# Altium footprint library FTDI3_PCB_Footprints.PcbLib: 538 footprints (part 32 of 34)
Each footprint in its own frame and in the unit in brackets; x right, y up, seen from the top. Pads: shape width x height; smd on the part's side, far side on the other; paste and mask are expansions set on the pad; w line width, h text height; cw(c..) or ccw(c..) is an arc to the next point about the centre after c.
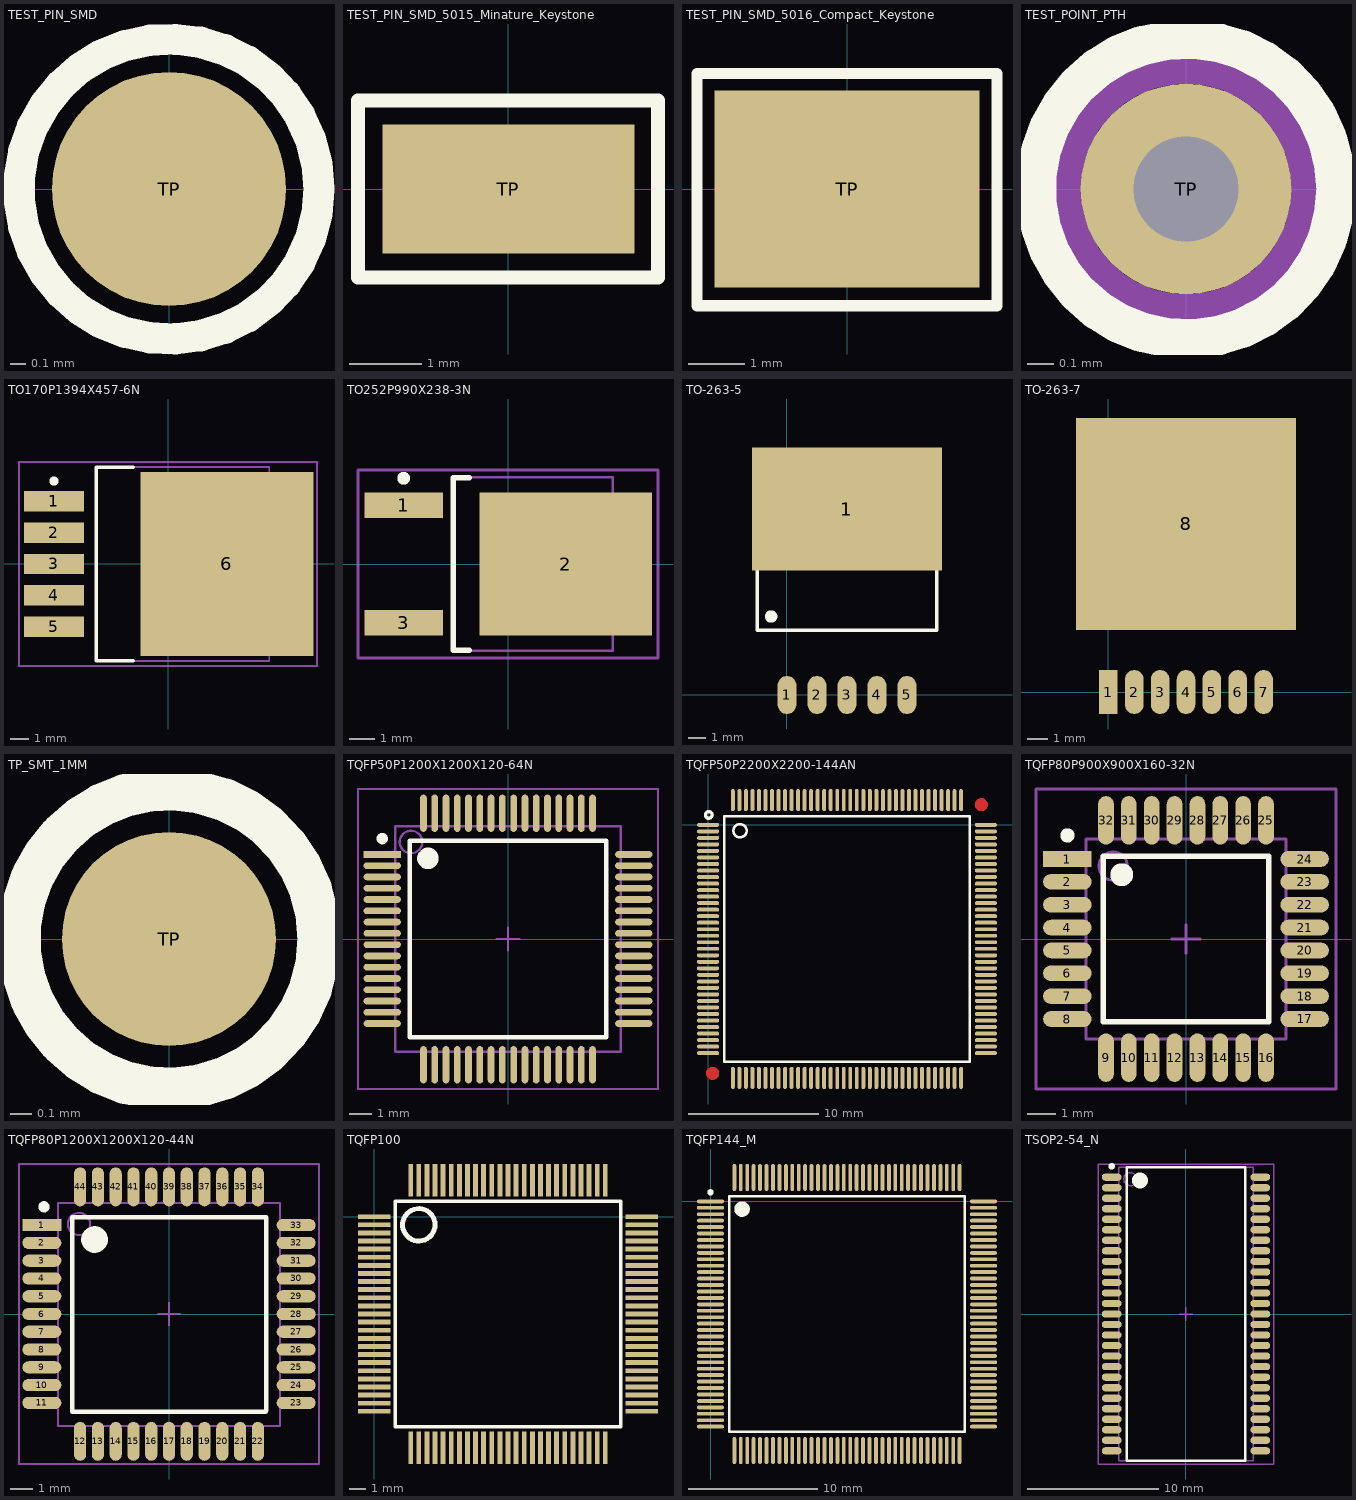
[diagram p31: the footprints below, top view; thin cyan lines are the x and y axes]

## TEST_PIN_SMD [mm] "Test pin; SMD"
pads (1):
  round 1.5 smd: TP(0,0)
Top Overlay:
  circle w0.2: c0,0 r0.96
M13_Assembly_Info keep-out:
  circle w0.1: c0,0 r0.96
3D body: height 0, standoff 0, extent -0.96,-0.97 0.96,0.95

## TEST_PIN_SMD_5015_Minature_Keystone [mm] "Test pin; SMD; 5015; Keystone"
height 1.52
pads (1):
  rect 3.5x1.8 smd: TP(0,0)
Top Overlay:
  lines w0.2: -2.09,-1.23 2.08,-1.23 2.08,1.23 -2.09,1.23 -2.09,-1.23

## TEST_PIN_SMD_5016_Compact_Keystone [mm] "Test pin; SMD; 5016; Keystone"
pads (1):
  rect 4.7x3.5 smd: TP(0,0)
Top Overlay:
  lines w0.2: -2.66,-2.07 -2.66,2.05 2.66,2.05 2.66,-2.07 -2.66,-2.07

## TEST_POINT_PTH [mm] "Test point for scope probe"
height 4.6
pads (1):
  round 0.8 hole 0.4: TP(0,0)
Top Overlay:
  circle w0.15: c0,0 r0.57
M13_Assembly_Info:
  circle w0.1: c0,0 r0.45

## TO170P1394X457-6N [mm] "D2-PAK, 6-Pads, Body 9.4x10.5mm (max), IPC Medium Density"
height 4.572
pads (6):
  rect 3.25x1.1 smd: 1(-6.2,3.404) 2(-6.2,1.702) 3(-6.2,0) 4(-6.2,-1.702) 5(-6.2,-3.404)
  rect 9.4x10 smd: 6(3.2,0)
Top Overlay:
  circle w0.25: c-6.2,4.504 r0.125
  lines w0.2: -1.9,-5.25 -3.9,-5.25 -3.9,5.25 -1.9,5.25
M13_Assembly_Info:
  lines w0.1: -3.9,-5.275 5.5,-5.275 5.5,5.275 -3.9,5.275 -3.9,-5.275
M15_Country_Yard:
  lines w0.1: -0.5,0 0.5,0 ; 0,-0.5 0,0.5 ; -8.1,-5.55 8.1,-5.55 8.1,5.55 -8.1,5.55 -8.1,-5.55
3D body: height 4.57, standoff 0.31, extent -3.9,-5.275 5.5,5.275

## TO252P990X238-3N [mm] "D-PAK, 3-Pads, Body 6.2x6.7mm (max), IPC Medium Density"
height 2.38
pads (3):
  rect 3.05x1 smd: 1(-4.05,2.28) 3(-4.05,-2.28)
  rect 6.7x5.55 smd: 2(2.25,0)
Top Overlay:
  circle w0.25: c-4.05,3.33 r0.125
  lines w0.2: -1.5,-3.35 -2.125,-3.35 -2.125,3.35 -1.5,3.35
M13_Assembly_Info:
  lines w0.1: -2.15,-3.375 4.07,-3.375 4.07,3.375 -2.15,3.375 -2.15,-3.375
M15_Country_Yard:
  lines w0.1: -0.5,0 0.5,0 ; 0,-0.5 0,0.5 ; -5.825,-3.65 5.825,-3.65 5.825,3.65 -5.825,3.65 -5.825,-3.65
3D body: height 2.38, standoff 0.13, extent -2.15,-3.375 4.07,3.375

## TO-263-5 [mil]
pads (6):
  oval 42x85 smd: 1(0,0) 2(67,0) 3(134,0) 4(201,0) 5(268,0)
  rect 425x275 smd: 1(134.02,415)
Top Overlay:
  circle w19.68: c-35.43,175.2 r3.94
  lines w7.87: -66,460 334,460 ; -66,145 334,145 334,485 -66,485 -66,145

## TO-263-7 [mil] "TO-263-7pin SMT package"
pads (8):
  rect 35.98x85 smd: 1(0,0)
  oval 36x85 smd: 2(50,0) 3(100,0) 4(150,0) 5(200,0) 6(250,0) 7(300,0)
  rect 425x410 smd: 8(150,325)
Top Overlay:
  circle w10: c-20,160 r10
  lines w7.87: -50,440 350,440 ; -50,130 -50,470 350,470 350,130 -50,130

## TP_SMT_1MM [mm]
pads (1):
  round 1 smd paste-1: TP(0,0)
Top Overlay:
  circle w0.2: c0,0 r0.7

## TQFP50P1200X1200X120-64N [mm] "TQFP, 64-Leads, Body 12.0x12.0mm (max), Pitch 0.50mm, IPC Medium Density"
height 1.2
pads (64):
  rect 1.65x0.3 smd: 1(-5.575,3.75)
  oval 1.65x0.3 smd: 2(-5.575,3.25) 3(-5.575,2.75) 4(-5.575,2.25) 5(-5.575,1.75) 6(-5.575,1.25) 7(-5.575,0.75) 8(-5.575,0.25) 9(-5.575,-0.25) 10(-5.575,-0.75) 11(-5.575,-1.25) 12(-5.575,-1.75) 13(-5.575,-2.25) 14(-5.575,-2.75) 15(-5.575,-3.25) 16(-5.575,-3.75) 33(5.575,-3.75) 34(5.575,-3.25) 35(5.575,-2.75) 36(5.575,-2.25) 37(5.575,-1.75) 38(5.575,-1.25) 39(5.575,-0.75) 40(5.575,-0.25) 41(5.575,0.25) 42(5.575,0.75) 43(5.575,1.25) 44(5.575,1.75) 45(5.575,2.25) 46(5.575,2.75) 47(5.575,3.25) 48(5.575,3.75)
  oval 0.3x1.65 smd: 17(-3.75,-5.575) 18(-3.25,-5.575) 19(-2.75,-5.575) 20(-2.25,-5.575) 21(-1.75,-5.575) 22(-1.25,-5.575) 23(-0.75,-5.575) 24(-0.25,-5.575) 25(0.25,-5.575) 26(0.75,-5.575) 27(1.25,-5.575) 28(1.75,-5.575) 29(2.25,-5.575) 30(2.75,-5.575) 31(3.25,-5.575) 32(3.75,-5.575) 49(3.75,5.575) 50(3.25,5.575) 51(2.75,5.575) 52(2.25,5.575) 53(1.75,5.575) 54(1.25,5.575) 55(0.75,5.575) 56(0.25,5.575) 57(-0.25,5.575) 58(-0.75,5.575) 59(-1.25,5.575) 60(-1.75,5.575) 61(-2.25,5.575) 62(-2.75,5.575) 63(-3.25,5.575) 64(-3.75,5.575)
Top Overlay:
  circle w0.25: c-5.575,4.45 r0.125
  circle w0.6: c-3.55,3.575 r0.175
  lines w0.2: -4.35,-4.35 -4.35,4.35 4.35,4.35 4.35,-4.35 -4.35,-4.35
M13_Assembly_Info:
  circle w0.1: c-4.3,4.3 r0.5
  lines w0.1: -5,-5 -5,5 5,5 5,-5 -5,-5
M15_Country_Yard:
  lines w0.1: -0.5,0 0.5,0 ; 0,-0.5 0,0.5 ; -6.65,-6.65 -6.65,6.65 6.65,6.65 6.65,-6.65 -6.65,-6.65
3D body: height 1.2, standoff 0.15, extent -5,-5 5,5

## TQFP50P2200X2200-144AN [mm] "Thin QFP, 144-Leads, Body 20x20mm, Pitch 0.5mm"
pads (144):
  oval 1.7x0.3 smd: 1(0,0) 2(0,-0.5) 3(0,-1) 4(0,-1.5) 5(0,-2) 6(0,-2.5) 7(0,-3) 8(0,-3.5) 9(0,-4) 10(0,-4.5) 11(0,-5) 12(0,-5.5) 13(0,-6) 14(0,-6.5) 15(0,-7) 16(0,-7.5) 17(0,-8) 18(0,-8.5) 19(0,-9) 20(0,-9.5) 21(0,-10) 22(0,-10.5) 23(0,-11) 24(0,-11.5) 25(0,-12) 26(0,-12.5) 27(0,-13) 28(0,-13.5) 29(0,-14) 30(0,-14.5) 31(0,-15) 32(0,-15.5) 33(0,-16) 34(0,-16.5) 35(0,-17) 36(0,-17.5) 73(21.3,-17.5) 74(21.3,-17) 75(21.3,-16.5) 76(21.3,-16) 77(21.3,-15.5) 78(21.3,-15) 79(21.3,-14.5) 80(21.3,-14) 81(21.3,-13.5) 82(21.3,-13) 83(21.3,-12.5) 84(21.3,-12) 85(21.3,-11.5) 86(21.3,-11) 87(21.3,-10.5) 88(21.3,-10) 89(21.3,-9.5) 90(21.3,-9) 91(21.3,-8.5) 92(21.3,-8) 93(21.3,-7.5) 94(21.3,-7) 95(21.3,-6.5) 96(21.3,-6) 97(21.3,-5.5) 98(21.3,-5) 99(21.3,-4.5) 100(21.3,-4) 101(21.3,-3.5) 102(21.3,-3) 103(21.3,-2.5) 104(21.3,-2) 105(21.3,-1.5) 106(21.3,-1) 107(21.3,-0.5) 108(21.3,0)
  oval 0.3x1.7 smd: 37(1.9,-19.4) 38(2.4,-19.4) 39(2.9,-19.4) 40(3.4,-19.4) 41(3.9,-19.4) 42(4.4,-19.4) 43(4.9,-19.4) 44(5.4,-19.4) 45(5.9,-19.4) 46(6.4,-19.4) 47(6.9,-19.4) 48(7.4,-19.4) 49(7.9,-19.4) 50(8.4,-19.4) 51(8.9,-19.4) 52(9.4,-19.4) 53(9.9,-19.4) 54(10.4,-19.4) 55(10.9,-19.4) 56(11.4,-19.4) 57(11.9,-19.4) 58(12.4,-19.4) 59(12.9,-19.4) 60(13.4,-19.4) 61(13.9,-19.4) 62(14.4,-19.4) 63(14.9,-19.4) 64(15.4,-19.4) 65(15.9,-19.4) 66(16.4,-19.4) 67(16.9,-19.4) 68(17.4,-19.4) 69(17.9,-19.4) 70(18.4,-19.4) 71(18.9,-19.4) 72(19.4,-19.4) 109(19.4,1.9) 110(18.9,1.9) 111(18.4,1.9) 112(17.9,1.9) 113(17.4,1.9) 114(16.9,1.9) 115(16.4,1.9) 116(15.9,1.9) 117(15.4,1.9) 118(14.9,1.9) 119(14.4,1.9) 120(13.9,1.9) 121(13.4,1.9) 122(12.9,1.9) 123(12.4,1.9) 124(11.9,1.9) 125(11.4,1.9) 126(10.9,1.9) 127(10.4,1.9) 128(9.9,1.9) 129(9.4,1.9) 130(8.9,1.9) 131(8.4,1.9) 132(7.9,1.9) 133(7.4,1.9) 134(6.9,1.9) 135(6.4,1.9) 136(5.9,1.9) 137(5.4,1.9) 138(4.9,1.9) 139(4.4,1.9) 140(3.9,1.9) 141(3.4,1.9) 142(2.9,1.9) 143(2.4,1.9) 144(1.9,1.9)
Top Layer:
  circle w0.5: c0.35,-19.05 r0.255
  circle w0.5: c20.95,1.55 r0.25
Top Overlay:
  circle w0.2: c2.45,-0.45 r0.51
  circle w0.254: c0.054,0.762 r0.254
  lines w0.2: 1.25,-18.15 20.05,-18.15 20.05,0.65 1.25,0.65 1.25,-18.15

## TQFP80P900X900X160-32N [mm] "TQFP, 32-Leads, Body 9.2x9.2mm (max), Pitch 0.80mm, IPC Medium Density"
height 1.6
pads (32):
  rect 1.7x0.55 smd: 1(-4.15,2.8)
  oval 1.7x0.55 smd: 2(-4.15,2) 3(-4.15,1.2) 4(-4.15,0.4) 5(-4.15,-0.4) 6(-4.15,-1.2) 7(-4.15,-2) 8(-4.15,-2.8) 17(4.15,-2.8) 18(4.15,-2) 19(4.15,-1.2) 20(4.15,-0.4) 21(4.15,0.4) 22(4.15,1.2) 23(4.15,2) 24(4.15,2.8)
  oval 0.55x1.7 smd: 9(-2.8,-4.15) 10(-2,-4.15) 11(-1.2,-4.15) 12(-0.4,-4.15) 13(0.4,-4.15) 14(1.2,-4.15) 15(2,-4.15) 16(2.8,-4.15) 25(2.8,4.15) 26(2,4.15) 27(1.2,4.15) 28(0.4,4.15) 29(-0.4,4.15) 30(-1.2,4.15) 31(-2,4.15) 32(-2.8,4.15)
Top Overlay:
  circle w0.25: c-4.15,3.625 r0.125
  circle w0.6: c-2.25,2.25 r0.1
  lines w0.2: -2.9,-2.9 -2.9,2.9 2.9,2.9 2.9,-2.9 -2.9,-2.9
M13_Assembly_Info:
  circle w0.1: c-2.55,2.55 r0.5
  lines w0.1: -3.5,-3.5 -3.5,3.5 3.5,3.5 3.5,-3.5 -3.5,-3.5
M15_Country_Yard:
  lines w0.1: -0.5,0 0.5,0 ; 0,-0.5 0,0.5 ; -5.25,-5.25 -5.25,5.25 5.25,5.25 5.25,-5.25 -5.25,-5.25
3D body: height 1.6, standoff 0.1, extent -3.5,-3.5 3.5,3.5

## TQFP80P1200X1200X120-44N [mm] "TQFP, 44-Leads, Body 12.3x12.3mm (max), Pitch 0.80mm, IPC Medium Density"
height 1.2
pads (44):
  rect 1.75x0.55 smd: 1(-5.72,4)
  oval 1.75x0.55 smd: 2(-5.72,3.2) 3(-5.72,2.4) 4(-5.72,1.6) 5(-5.72,0.8) 6(-5.72,0) 7(-5.72,-0.8) 8(-5.72,-1.6) 9(-5.72,-2.4) 10(-5.72,-3.2) 11(-5.72,-4) 23(5.72,-4) 24(5.72,-3.2) 25(5.72,-2.4) 26(5.72,-1.6) 27(5.72,-0.8) 28(5.72,0) 29(5.72,0.8) 30(5.72,1.6) 31(5.72,2.4) 32(5.72,3.2) 33(5.72,4)
  oval 0.55x1.75 smd: 12(-4,-5.73) 13(-3.2,-5.73) 14(-2.4,-5.73) 15(-1.6,-5.73) 16(-0.8,-5.73) 17(0,-5.73) 18(0.8,-5.73) 19(1.6,-5.73) 20(2.4,-5.73) 21(3.2,-5.73) 22(4,-5.73) 34(4,5.72) 35(3.2,5.72) 36(2.4,5.72) 37(1.6,5.72) 38(0.8,5.72) 39(0,5.72) 40(-0.8,5.72) 41(-1.6,5.72) 42(-2.4,5.72) 43(-3.2,5.72) 44(-4,5.72)
Top Overlay:
  circle w0.25: c-5.625,4.825 r0.125
  circle w0.6: c-3.35,3.35 r0.3
  lines w0.2: -4.35,-4.39 4.35,-4.39 ; -4.35,-4.35 -4.35,4.35 4.35,4.35 ; 4.38,-4.35 4.38,4.35
M13_Assembly_Info:
  circle w0.1: c-4.05,4.05 r0.5
  lines w0.1: -5,-5.04 5,-5.04 ; -5,-5 -5,5 5,5 5,-5
M15_Country_Yard:
  lines w0.1: -0.5,0 0.5,0 ; 0,-0.5 0,0.5 ; -6.75,-6.75 -6.75,6.75 6.75,6.75 6.75,-6.75 -6.75,-6.75
3D body: height 1.2, standoff 0.15, extent -5,-5 5,5

## TQFP100 [mm]
pads (100):
  rect 2x0.3 smd: 1(0,0) 2(0,-0.5) 3(0,-1) 4(0,-1.5) 5(0,-2) 6(0,-2.5) 7(0,-3) 8(0,-3.5) 9(0,-4) 10(0,-4.5) 11(0,-5) 12(0,-5.5) 13(0,-6) 14(0,-6.5) 15(0,-7) 16(0,-7.5) 17(0,-8) 18(0,-8.5) 19(0,-9) 20(0,-9.5) 21(0,-10) 22(0,-10.5) 23(0,-11) 24(0,-11.5) 25(0,-12) 51(16.5,-12) 52(16.5,-11.5) 53(16.5,-11) 54(16.5,-10.5) 55(16.5,-10) 56(16.5,-9.5) 57(16.5,-9) 58(16.5,-8.5) 59(16.5,-8) 60(16.5,-7.5) 61(16.5,-7) 62(16.5,-6.5) 63(16.5,-6) 64(16.5,-5.5) 65(16.5,-5) 66(16.5,-4.5) 67(16.5,-4) 68(16.5,-3.5) 69(16.5,-3) 70(16.5,-2.5) 71(16.5,-2) 72(16.5,-1.5) 73(16.5,-1) 74(16.5,-0.5) 75(16.5,0)
  rect 0.3x2 smd: 26(2.25,-14.25) 27(2.75,-14.25) 28(3.25,-14.25) 29(3.75,-14.25) 30(4.25,-14.25) 31(4.75,-14.25) 32(5.25,-14.25) 33(5.75,-14.25) 34(6.25,-14.25) 35(6.75,-14.25) 36(7.25,-14.25) 37(7.75,-14.25) 38(8.25,-14.25) 39(8.75,-14.25) 40(9.25,-14.25) 41(9.75,-14.25) 42(10.25,-14.25) 43(10.75,-14.25) 44(11.25,-14.25) 45(11.75,-14.25) 46(12.25,-14.25) 47(12.75,-14.25) 48(13.25,-14.25) 49(13.75,-14.25) 50(14.25,-14.25) 76(14.25,2.25) 77(13.75,2.25) 78(13.25,2.25) 79(12.75,2.25) 80(12.25,2.25) 81(11.75,2.25) 82(11.25,2.25) 83(10.75,2.25) 84(10.25,2.25) 85(9.75,2.25) 86(9.25,2.25) 87(8.75,2.25) 88(8.25,2.25) 89(7.75,2.25) 90(7.25,2.25) 91(6.75,2.25) 92(6.25,2.25) 93(5.75,2.25) 94(5.25,2.25) 95(4.75,2.25) 96(4.25,2.25) 97(3.75,2.25) 98(3.25,2.25) 99(2.75,2.25) 100(2.25,2.25)
Top Overlay:
  circle w0.305: c2.75,-0.5 r1
  lines w0.2: 1.29,-12.949 15.21,-12.949 15.21,0.949 1.29,0.949 1.29,-12.949

## TQFP144_M [mm] "Thin QFP, 144-Leads, Body 20x20mm, Pitch 0.5mm, IPC Low Density"
height 1.6
pads (144):
  oval 2.1x0.3 smd: 1(0,0) 2(0,-0.5) 3(0,-1) 4(0,-1.5) 5(0,-2) 6(0,-2.5) 7(0,-3) 8(0,-3.5) 9(0,-4) 10(0,-4.5) 11(0,-5) 12(0,-5.5) 13(0,-6) 14(0,-6.5) 15(0,-7) 16(0,-7.5) 17(0,-8) 18(0,-8.5) 19(0,-9) 20(0,-9.5) 21(0,-10) 22(0,-10.5) 23(0,-11) 24(0,-11.5) 25(0,-12) 26(0,-12.5) 27(0,-13) 28(0,-13.5) 29(0,-14) 30(0,-14.5) 31(0,-15) 32(0,-15.5) 33(0,-16) 34(0,-16.5) 35(0,-17) 36(0,-17.5) 73(21.2,-17.5) 74(21.2,-17) 75(21.2,-16.5) 76(21.2,-16) 77(21.2,-15.5) 78(21.2,-15) 79(21.2,-14.5) 80(21.2,-14) 81(21.2,-13.5) 82(21.2,-13) 83(21.2,-12.5) 84(21.2,-12) 85(21.2,-11.5) 86(21.2,-11) 87(21.2,-10.5) 88(21.2,-10) 89(21.2,-9.5) 90(21.2,-9) 91(21.2,-8.5) 92(21.2,-8) 93(21.2,-7.5) 94(21.2,-7) 95(21.2,-6.5) 96(21.2,-6) 97(21.2,-5.5) 98(21.2,-5) 99(21.2,-4.5) 100(21.2,-4) 101(21.2,-3.5) 102(21.2,-3) 103(21.2,-2.5) 104(21.2,-2) 105(21.2,-1.5) 106(21.2,-1) 107(21.2,-0.5) 108(21.2,0)
  oval 0.3x2.1 smd: 37(1.85,-19.35) 38(2.35,-19.35) 39(2.85,-19.35) 40(3.35,-19.35) 41(3.85,-19.35) 42(4.35,-19.35) 43(4.85,-19.35) 44(5.35,-19.35) 45(5.85,-19.35) 46(6.35,-19.35) 47(6.85,-19.35) 48(7.35,-19.35) 49(7.85,-19.35) 50(8.35,-19.35) 51(8.85,-19.35) 52(9.35,-19.35) 53(9.85,-19.35) 54(10.35,-19.35) 55(10.85,-19.35) 56(11.35,-19.35) 57(11.85,-19.35) 58(12.35,-19.35) 59(12.85,-19.35) 60(13.35,-19.35) 61(13.85,-19.35) 62(14.35,-19.35) 63(14.85,-19.35) 64(15.35,-19.35) 65(15.85,-19.35) 66(16.35,-19.35) 67(16.85,-19.35) 68(17.35,-19.35) 69(17.85,-19.35) 70(18.35,-19.35) 71(18.85,-19.35) 72(19.35,-19.35) 109(19.35,1.85) 110(18.85,1.85) 111(18.35,1.85) 112(17.85,1.85) 113(17.35,1.85) 114(16.85,1.85) 115(16.35,1.85) 116(15.85,1.85) 117(15.35,1.85) 118(14.85,1.85) 119(14.35,1.85) 120(13.85,1.85) 121(13.35,1.85) 122(12.85,1.85) 123(12.35,1.85) 124(11.85,1.85) 125(11.35,1.85) 126(10.85,1.85) 127(10.35,1.85) 128(9.85,1.85) 129(9.35,1.85) 130(8.85,1.85) 131(8.35,1.85) 132(7.85,1.85) 133(7.35,1.85) 134(6.85,1.85) 135(6.35,1.85) 136(5.85,1.85) 137(5.35,1.85) 138(4.85,1.85) 139(4.35,1.85) 140(3.85,1.85) 141(3.35,1.85) 142(2.85,1.85) 143(2.35,1.85) 144(1.85,1.85)
Top Overlay:
  circle w0.6: c2.45,-0.6 r0.3
  circle w0.25: c0,0.7 r0.125
  lines w0.2: 1.45,-17.9 19.75,-17.9 19.75,0.4 1.45,0.4 1.45,-17.9

## TSOP2-54_N [mm] "SOP, 54-Leads, Body 22.2x10.16mm, Pitch 0.8mm, IPC Medium Density"
height 1.2
pads (54):
  oval 1.5x0.55 smd: 1(-5.65,10.4) 2(-5.65,9.6) 3(-5.65,8.8) 4(-5.65,8) 5(-5.65,7.2) 6(-5.65,6.4) 7(-5.65,5.6) 8(-5.65,4.8) 9(-5.65,4) 10(-5.65,3.2) 11(-5.65,2.4) 12(-5.65,1.6) 13(-5.65,0.8) 14(-5.65,0) 15(-5.65,-0.8) 16(-5.65,-1.6) 17(-5.65,-2.4) 18(-5.65,-3.2) 19(-5.65,-4) 20(-5.65,-4.8) 21(-5.65,-5.6) 22(-5.65,-6.4) 23(-5.65,-7.2) 24(-5.65,-8) 25(-5.65,-8.8) 26(-5.65,-9.6) 27(-5.65,-10.4) 28(5.65,-10.4) 29(5.65,-9.6) 30(5.65,-8.8) 31(5.65,-8) 32(5.65,-7.2) 33(5.65,-6.4) 34(5.65,-5.6) 35(5.65,-4.8) 36(5.65,-4) 37(5.65,-3.2) 38(5.65,-2.4) 39(5.65,-1.6) 40(5.65,-0.8) 41(5.65,0) 42(5.65,0.8) 43(5.65,1.6) 44(5.65,2.4) 45(5.65,3.2) 46(5.65,4) 47(5.65,4.8) 48(5.65,5.6) 49(5.65,6.4) 50(5.65,7.2) 51(5.65,8) 52(5.65,8.8) 53(5.65,9.6) 54(5.65,10.4)
Top Overlay:
  circle w0.25: c-5.65,11.225 r0.125
  circle w0.6: c-3.5,10.15 r0.3
  lines w0.2: -4.5,-11.15 -4.5,11.15 4.5,11.15 4.5,-11.15 -4.5,-11.15
M13_Assembly_Info:
  circle w0.1: c-4.22,10.25 r0.5
  lines w0.1: -5.12,-11.15 -5.12,11.15 5.12,11.15 5.12,-11.15 -5.12,-11.15
M15_Country_Yard:
  lines w0.1: -0.5,0 0.5,0 ; 0,-0.5 0,0.5 ; -6.65,-11.4 -6.65,11.4 6.65,11.4 6.65,-11.4 -6.65,-11.4
3D body: height 1.2, standoff 0, extent -5.12,-11.15 5.12,11.15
